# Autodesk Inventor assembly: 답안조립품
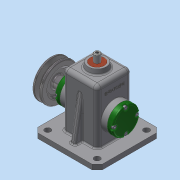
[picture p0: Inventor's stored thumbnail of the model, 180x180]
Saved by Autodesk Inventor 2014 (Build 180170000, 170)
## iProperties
Created: 2016-02
Part Number: 답안조립품
Document SubType Name: Assembly
Designer: 406-강의용
Author: 406-강의용
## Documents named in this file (15)
- C:\Users\406-강의용\Desktop\460211V1020\답안조립품.iam
- C:\Users\406-강의용\Desktop\460211V1020\본체.ipt
- C:\Users\406-강의용\Desktop\460211V1020\뒤커버.ipt
- C:\Users\406-강의용\Desktop\460211V1020\앞커버.ipt
- C:\Users\406-강의용\Desktop\460211V1020\베어링 12 x 32 x 10.ipt
- C:\Users\406-강의용\Desktop\460211V1020\편심축.ipt
- C:\Users\406-강의용\Desktop\460211V1020\링크.ipt
- C:\Users\406-강의용\Desktop\460211V1020\핀 5 x 18.ipt
- C:\Users\406-강의용\Desktop\460211V1020\슬라이드.ipt
- C:\Users\406-강의용\Desktop\460211V1020\부시.ipt
- C:\Users\406-강의용\Desktop\460211V1020\키 4 x 4 x 10.ipt
- C:\Users\406-강의용\Desktop\460211V1020\V벨트풀리.ipt
- C:\Users\406-강의용\Desktop\460211V1020\멈춤나사 M3x8.ipt
- C:\Users\406-강의용\Desktop\460211V1020\고정핀 1.2 x 10.ipt
- C:\Users\406-강의용\Desktop\460211V1020\볼트 M4 x 12.ipt
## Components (11 placed, 4 different names)
1. 핀 5 x 18:1
2. V벨트풀리:1
3. 고정핀 1.2 x 10:1
4. ISO 4762 M4 x 12:1
5. ISO 4762 M4 x 12:3
6. ISO 4762 M4 x 12:4
7. ISO 4762 M4 x 12:5
8. ISO 4762 M4 x 12:2
9. ISO 4762 M4 x 12:6
10. ISO 4762 M4 x 12:7
11. ISO 4762 M4 x 12:8
